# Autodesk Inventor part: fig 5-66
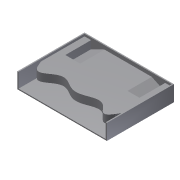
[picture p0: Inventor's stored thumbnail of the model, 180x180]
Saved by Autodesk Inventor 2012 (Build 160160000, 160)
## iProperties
Created: 2004-05
Part Number: fig 5-66
Document SubType Name: Modeling
Designer: CADCIM Technologies
Manufacturer: Standard
Standards Organization: Custom
Density: 1 g/cm^3
Material: Default
Author: CADCIM Technologies
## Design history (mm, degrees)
sketch "Sketch1"
  geometry: L1 (-40, -30)-(40, -30); L2 (40, -30)-(40, 30); L3 (40, 30)-(-40, 30); L4 (-40, 30)-(-40, -30); 1 further point
  constraints: 8 end point, 2 parallel, 1 horizontal, 1 perpendicular, 1 other
  dimensions: "d0" = 80 distance of L1.start L1.end; "d1" = 60 distance of L3.end L1.start; "d2" = 30 distance from line of point (0, 0) L1; "d3" = 40 distance from line of point (0, 0) L4
extrude "Extrusion1" new body sketch "Sketch1" distance "d4" = 14; taper "d5" = 0 deg
shell "Shell1" dims "d6" = 1
workplane "Work Plane1"
sketch "Sketch2"
  geometry: L1 (78, -13)-(78, -11.813); L2 (0, -11.813)-(0, -13); L3 (0, -13)-(78, -13); L4 (0, -11.813)-(17.826, -3.295); L5 (17.826, -3.295)-(60.174, -3.295); L6 (60.174, -3.295)-(78, -11.813); L7 (79, -13.795)-(78, -13.795); L8 (78, 0)-(78, -13) reference; L9 (0, -13)-(0, 0) reference; L10 (78, -13)-(0, -13) reference
  constraints: 14 end point, 3 collinear, 2 equal length, 2 vertical, 1 horizontal alignment, 1 parallel, 1 point on line
extrude "Extrusion2" join sketch "Sketch2" stored distance "d8" = 14; taper "d9" = 0 deg
workplane "Work Plane2"
sketch "Sketch3"
  geometry: 7 further points
  constraints: 7 other
extrude "Extrusion7" join sketch "Sketch3" distance "d27" = 7; taper "d28" = 0 deg
body "Solid1"
other parameters: "d7" = 23, "d18" = 4, "d29" = 7
